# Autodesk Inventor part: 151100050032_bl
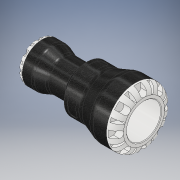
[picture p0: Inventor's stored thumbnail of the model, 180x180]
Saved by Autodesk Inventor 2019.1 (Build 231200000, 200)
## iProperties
Created: 2016-12
Part Number: 151100050032_bl
Material: PVC-Piping
Description: PLASSON G-PLASS  REDUCING COUPLING  50 x 32
Document SubType Name: Modeling
Designer: KIM
Mass: 309.689 g
Surface Area: 488.063 cm^2
Volume: 221.206 cm^3
Density: 1.4 g/cm^3
Appearance: Black Cast
Author: KIM
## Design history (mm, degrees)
derived "151100.ipt"
feature "Solid1::151100.ipt" dims "ScaleForDerivedMember" = 10
tag "TaggingFeature1"
body "Solid1"
other parameters: "d0" = 158 [user parameter], "d2" = 34.86 [user parameter], "d4" = 85 [user parameter], "d6" = 83 [user parameter], "d7" = 4.16667 [user parameter], "d8" = 58 [user parameter], "d9" = 32 [user parameter], "d11" = 23.94 [user parameter], "d12" = 57 [user parameter], "d13" = 2.66667 [user parameter], "d14" = 68 [user parameter], "d15" = 46.4 [user parameter], "d16" = 20 deg [user parameter], "d17" = 20 deg [user parameter], "d18" = 130 deg [user parameter], "d26" = 0 [user parameter], "d28" = 360 deg [user parameter], "d30" = 8 deg [user parameter], "d31" = 1 [user parameter], "d32" = 8 deg [user parameter], "d33" = 1 [user parameter], "d35" = 0 [user parameter], "d37" = 360 deg [user parameter], "d39" = 7.2 [user parameter], "d42" = 7.2 [user parameter], "d43" = 0 [user parameter], "d45" = 360 deg [user parameter], "d47" = 0.64 [user parameter], "d48" = 8 deg [user parameter], "d49" = 8 deg [user parameter], "d50" = 0.64 [user parameter], "d52" = 0 [user parameter], "d54" = 360 deg [user parameter], "d56" = 11.6 [user parameter], "d57" = 17 [user parameter], "d58" = 0.5 [user parameter], "d60" = 10.2 [user parameter], "d61" = 12.5 [user parameter], "d62" = 16.2 [user parameter], "d63" = 0 [user parameter], "d66" = 0 [user parameter], "d68" = 360 deg [user parameter], "d75" = 10.74673 [user parameter], "d77" = 66.3 [user parameter], "d78" = 0.85 [user parameter], "d1" = 32 [user parameter], "E_" = 85 [user parameter], "H_" = 158 [user parameter], "l_" = 83 [user parameter], "E1" = 58 [user parameter], "l1" = 57 [user parameter], "Plasson" = 1 [user parameter], "d20" = 9 [user parameter], "d21" = 12.5 [user parameter], "d23" = 85 [user parameter], "d40" = 58 [user parameter], "d59" = 21.49345 [user parameter]
